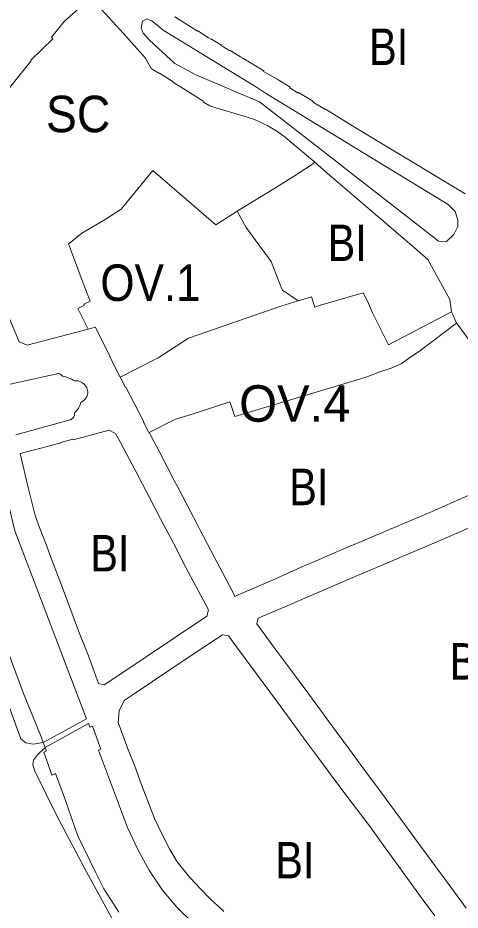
# Model space of a CAD drawing. Extents: x -650451 to -642268, y -1075216 to -1066610.
# Drawn here: x -647183 to -647037.6, y -1071143.1 to -1070849.7 of the extents above; entities that cross this region are included whole.
import ezdxf

# ---------------------------------------------------------------- set-up
doc = ezdxf.new("R2010")
doc.units = 0
doc.header["$LTSCALE"] = 4.8
for name, color, linetype, lineweight in [('1', 7, 'Continuous', 13), ('11', 7, 'Continuous', 13), ('15', 7, 'Continuous', 13), ('17', 7, 'Continuous', 13), ('2', 7, 'Continuous', 13), ('40', 7, 'Continuous', 13), ('45', 7, 'Continuous', 13)]:
    doc.layers.add(name, color=color, linetype=linetype, lineweight=lineweight)
doc.layers.add('62', color=7, linetype='Continuous')

msp = doc.modelspace()

# ---------------------------------------------------------------- linework, layer by layer
at = {"layer": '1'}
for points in [[(-647204.055, -1071005.609), (-647203.96, -1071005.88), (-647199.63, -1071026.94), (-647195.64, -1071044.04), (-647194.61, -1071048.68), (-647192.72, -1071055.27), (-647189.68, -1071065.99), (-647181.99, -1071086.74), (-647180.4, -1071088.08), (-647177.94, -1071088.5), (-647174.64, -1071088.01), (-647174.03, -1071089.6)], [(-647174.03, -1071089.6), (-647176.58, -1071092.03), (-647177.89, -1071093.78), (-647178.11, -1071095.31), (-647177.46, -1071097.42), (-647170.18, -1071112.08), (-647161.13, -1071129.3), (-647146.28, -1071156.35), (-647135.21, -1071176.44), (-647130.1, -1071184.33), (-647129.04, -1071186.06), (-647125.44, -1071192.58), (-647123.7, -1071196.19), (-647106.7, -1071234.45), (-647104.17, -1071235.6)]]:
    msp.add_lwpolyline(points, dxfattribs=at)
at = {"layer": '11'}
for points in [[(-647159.85, -1070952.1), (-647163.28, -1070945.32), (-647161.07, -1070944.22), (-647161.27, -1070943.82), (-647159.26, -1070942.81), (-647161.48, -1070936.91), (-647165.05, -1070927.47), (-647166.38, -1070924.05), (-647165.6, -1070923.42), (-647161.98, -1070920.55), (-647154.33, -1070916.01), (-647148.98, -1070912.65), (-647138.65, -1070899.94), (-647117.95, -1070917.77), (-647110.92, -1070913.23)], [(-647110.92, -1070913.23), (-647107.9, -1070918.58), (-647104.06, -1070923.89), (-647099.76, -1070929.83), (-647096.5, -1070937.98), (-647095.97, -1070939.29), (-647090.82, -1070942.76)], [(-647090.82, -1070942.76), (-647086.45, -1070941.45), (-647085.35, -1070944.79), (-647083.51, -1070944.2), (-647069.41, -1070940.13), (-647068.07, -1070942.91), (-647066.38, -1070946.67), (-647061.16, -1070957.22), (-647040.4, -1070946.32)], [(-647090.82, -1070942.76), (-647096.57, -1070944.49), (-647126.93, -1070955.01), (-647136.81, -1070961.5), (-647149.39, -1070967.8)], [(-647149.39, -1070967.8), (-647136.81, -1070961.5), (-647126.93, -1070955.01), (-647096.57, -1070944.49), (-647090.82, -1070942.76)], [(-647040.4, -1070946.32), (-647039.98, -1070947.27), (-647038.77, -1070950.05)], [(-647038.77, -1070950.05), (-647050.95, -1070959.26), (-647054.07, -1070961.43), (-647056.94, -1070963.42), (-647060.27, -1070964.9), (-647063.97, -1070966.14), (-647067.95, -1070967.65), (-647071.8, -1070968.86), (-647111.62, -1070980.84), (-647112.64, -1070977.86), (-647113.29, -1070975.92), (-647118.98, -1070977.8), (-647122.66, -1070978.98), (-647127.1, -1070980.41), (-647131.11, -1070981.71), (-647139.77, -1070986.03)], [(-647149.39, -1070967.8), (-647152.75, -1070961.18), (-647152.62, -1070961.11), (-647157.5, -1070951.41), (-647157.59, -1070951.46), (-647159.85, -1070952.1)], [(-647139.77, -1070986.03), (-647139.82, -1070985.92), (-647139.98, -1070986.03), (-647141.67, -1070982.64), (-647141.54, -1070982.55), (-647147.47, -1070971.18), (-647147.59, -1070971.24), (-647149.39, -1070967.8)]]:
    msp.add_lwpolyline(points, dxfattribs=at)
at = {"layer": '15'}
for points in [[(-647159.11, -1070843.05), (-647167.65, -1070850.81), (-647171.97, -1070856.04), (-647171.49, -1070856.55), (-647178.72, -1070863.64), (-647178.59, -1070863.81), (-647184.47, -1070871.02), (-647191.27, -1070879.56), (-647198.26, -1070888.32), (-647203.11, -1070894.33), (-647205.72, -1070897.57), (-647206.05, -1070898.36), (-647205.89, -1070899.27), (-647200.92, -1070911.38), (-647195.82, -1070923.93), (-647191.5, -1070934.48), (-647189.1, -1070940.36), (-647187.61, -1070944.13), (-647182.58, -1070956.24), (-647179.88, -1070957.38), (-647159.85, -1070952.1)], [(-647085.4, -1070897.14), (-647095.52, -1070888.57), (-647098.18, -1070886.71), (-647100.79, -1070885.17), (-647105.19, -1070883.09), (-647108.31, -1070882.14), (-647117.94, -1070879.25), (-647119.85, -1070878.57), (-647122, -1070877.41), (-647121.89, -1070877.25), (-647129.57, -1070872.37), (-647132.03, -1070870.82), (-647131.98, -1070870.73), (-647136.41, -1070867.92), (-647136.47, -1070868), (-647139.02, -1070866.44), (-647141.09, -1070862.83), (-647148.3, -1070854.79), (-647157.95, -1070844.35)], [(-647131.43, -1070849.34), (-647123.88, -1070854.09), (-647123.82, -1070853.99), (-647120.31, -1070856.28), (-647119.59, -1070856.68), (-647119.55, -1070856.6), (-647116.09, -1070858.66), (-647116.16, -1070858.77), (-647113.25, -1070860.52), (-647113.19, -1070860.43), (-647109.74, -1070862.55), (-647109.06, -1070862.97), (-647102.16, -1070867.16), (-647102.27, -1070867.33), (-647097.73, -1070869.9), (-647093.48, -1070872.53), (-647093.57, -1070872.69), (-647090.78, -1070874.43), (-647090.69, -1070874.28), (-647086.39, -1070876.9), (-647085.74, -1070877.4), (-647085.79, -1070877.49), (-647081.89, -1070879.84), (-647081.84, -1070879.77), (-647081.35, -1070880.06), (-647074.06, -1070884.49), (-647063.75, -1070890.75), (-647052.83, -1070897.35), (-647035.98, -1070907.53)], [(-647040.4, -1070946.32), (-647041.01, -1070942.31), (-647048.23, -1070929.16), (-647052.6, -1070925.35), (-647055.69, -1070922.66), (-647062.48, -1070916.84), (-647062.93, -1070916.46), (-647063.93, -1070915.6), (-647069.27, -1070911.03), (-647078.43, -1070903.2), (-647080.53, -1070901.41), (-647085.4, -1070897.14)], [(-647174.64, -1071088.01), (-647160.4, -1071080.2), (-647184, -1071018.37), (-647190.24, -1070992.73), (-647199.63, -1070950.26), (-647202.86, -1070940.4), (-647204.22, -1070937.43), (-647205.57, -1070934.86), (-647207.86, -1070930.75), (-647207.09, -1070930.4), (-647209.82, -1070924.75), (-647210.86, -1070925.29), (-647215.03, -1070918.17), (-647220.39, -1070910.9), (-647230.25, -1070922.01)], [(-647038.77, -1070950.05), (-647039.98, -1070947.27), (-647040.4, -1070946.32)], [(-647034.09, -1070956.5), (-647038.19, -1070950.73), (-647038.77, -1070950.05)], [(-647159.85, -1070952.1), (-647157.59, -1070951.46), (-647157.5, -1070951.41), (-647152.62, -1070961.11), (-647152.75, -1070961.18), (-647149.39, -1070967.8)], [(-647183.62, -1070986.82), (-647165.84, -1070981.83), (-647165.677, -1070981.79), (-647165.513, -1070981.734), (-647165.35, -1070981.66), (-647165.191, -1070981.569), (-647165.04, -1070981.459), (-647164.897, -1070981.333), (-647164.768, -1070981.19), (-647164.653, -1070981.035), (-647164.555, -1070980.868), (-647164.475, -1070980.692), (-647164.415, -1070980.512), (-647164.374, -1070980.329), (-647164.353, -1070980.147), (-647164.349, -1070979.968), (-647164.362, -1070979.795), (-647164.39, -1070979.63), (-647164.023, -1070979.279), (-647163.679, -1070978.898), (-647163.364, -1070978.49), (-647163.079, -1070978.058), (-647162.828, -1070977.607), (-647162.612, -1070977.138), (-647162.432, -1070976.658), (-647162.29, -1070976.17), (-647162.006, -1070976), (-647161.732, -1070975.812), (-647161.468, -1070975.606), (-647161.218, -1070975.384), (-647160.981, -1070975.147), (-647160.761, -1070974.896), (-647160.556, -1070974.633), (-647160.37, -1070974.36), (-647160.201, -1070973.97), (-647160.079, -1070973.551), (-647160.012, -1070973.112), (-647160.004, -1070972.664), (-647160.055, -1070972.219), (-647160.163, -1070971.788), (-647160.324, -1070971.382), (-647160.53, -1070971.01), (-647160.674, -1070970.78), (-647160.837, -1070970.558), (-647161.018, -1070970.343), (-647161.216, -1070970.14), (-647161.431, -1070969.949), (-647161.66, -1070969.773), (-647161.903, -1070969.613), (-647162.158, -1070969.471), (-647162.423, -1070969.349), (-647162.695, -1070969.246), (-647162.972, -1070969.164), (-647163.253, -1070969.103), (-647163.534, -1070969.062), (-647163.813, -1070969.042), (-647164.089, -1070969.042), (-647164.36, -1070969.06), (-647164.82, -1070968.802), (-647165.29, -1070968.561), (-647165.77, -1070968.339), (-647166.259, -1070968.136), (-647166.756, -1070967.952), (-647167.259, -1070967.788), (-647167.768, -1070967.644), (-647168.28, -1070967.52), (-647168.478, -1070967.276), (-647168.724, -1070967.059), (-647169.013, -1070966.883), (-647169.332, -1070966.757), (-647169.669, -1070966.69), (-647170.007, -1070966.683), (-647170.332, -1070966.732), (-647170.63, -1070966.83), (-647187.45, -1070970.63)], [(-647149.39, -1070967.8), (-647147.59, -1070971.24), (-647147.47, -1070971.18), (-647141.54, -1070982.55), (-647141.67, -1070982.64), (-647139.98, -1070986.03), (-647139.82, -1070985.92), (-647139.77, -1070986.03)], [(-647139.77, -1070986.03), (-647136.42, -1070992.4), (-647131.57, -1071001.79), (-647130.42, -1071003.99), (-647126.2, -1071012.05), (-647124.16, -1071016), (-647123.01, -1071018.21), (-647118.46, -1071026.92), (-647115.64, -1071032.28), (-647112.2, -1071038.81), (-647111.69, -1071039.93), (-647111.46, -1071039.83), (-647110.53, -1071039.41), (-647098.25, -1071034.12), (-647098.03, -1071034.02), (-647088.61, -1071029.83), (-647084.94, -1071028.2), (-647077.91, -1071025.19), (-647066.72, -1071020.44), (-647062.38, -1071018.6), (-647057.91, -1071016.75), (-647046.73, -1071012.03), (-647039.7, -1071008.85), (-647030.09, -1071004.71)], [(-647034.05, -1071017.19), (-647042.97, -1071021.07), (-647049.89, -1071023.99), (-647056.91, -1071026.94), (-647063.71, -1071029.85), (-647072.13, -1071033.43), (-647080, -1071036.81), (-647087.87, -1071040.16), (-647093.7, -1071042.7), (-647103.94, -1071047.15), (-647104.42, -1071049.02), (-647098.81, -1071056.61), (-647094.28, -1071062.75), (-647086.95, -1071072.55), (-647080.49, -1071081.41), (-647074, -1071090.26), (-647069.57, -1071096.31), (-647063.44, -1071104.55), (-647057.61, -1071112.44), (-647051.99, -1071120.09), (-647040.61, -1071135.59), (-647035.55, -1071142.45)], [(-647045.94, -1071145.04), (-647049.72, -1071139.82), (-647052.02, -1071136.62), (-647057.7, -1071128.79), (-647061.95, -1071123.11), (-647067.4, -1071115.37), (-647073.12, -1071107.95), (-647078.46, -1071100.83), (-647083.72, -1071093.74), (-647087.31, -1071088.82), (-647090.86, -1071084.05), (-647094.36, -1071079.2), (-647097.98, -1071074.28), (-647104.55, -1071065.44), (-647111.07, -1071056.53), (-647113.73, -1071052.94), (-647115.73, -1071052.54), (-647127.7, -1071060.49), (-647144.46, -1071071.76), (-647148, -1071074.23), (-647149.73, -1071077.63), (-647150.04, -1071081.39), (-647146.78, -1071090.05), (-647144.56, -1071095.83), (-647142.43, -1071101.58), (-647140.25, -1071107.27), (-647138.05, -1071112.99), (-647135.48, -1071118.5), (-647133.11, -1071122.94), (-647130.57, -1071127.29), (-647126.96, -1071131.77), (-647126.3, -1071132.51), (-647122.81, -1071136.22), (-647119.63, -1071139.51), (-647116.09, -1071142.83), (-647115.24, -1071143.6)], [(-647125.39, -1071147.43), (-647130.77, -1071142.19), (-647135.45, -1071136.55), (-647139.72, -1071130.15), (-647143.58, -1071123.16), (-647146.94, -1071115.94), (-647156.53, -1071090.49), (-647155.66, -1071090.17), (-647158.43, -1071082.62), (-647159.3, -1071082.95), (-647159.77, -1071081.77), (-647174.03, -1071089.6), (-647174.64, -1071088.01)]]:
    msp.add_lwpolyline(points, dxfattribs=at)
for points in [[(-647142.02, -1070850.81), (-647142.49, -1070852.95), (-647141.78, -1070854.71), (-647139.73, -1070857.02), (-647131.43, -1070864.72), (-647124.51, -1070868.42), (-647106.9, -1070875.89), (-647103.57, -1070877.32), (-647077.16, -1070897.85), (-647075.9, -1070898.84), (-647050.33, -1070918.71), (-647044.71, -1070923.08), (-647042.06, -1070923.25), (-647039.69, -1070920.97), (-647038.35, -1070918.28), (-647038.36, -1070916.27), (-647039.23, -1070913.32), (-647041.52, -1070911.06), (-647071.49, -1070892.79), (-647072.94, -1070891.9), (-647101.59, -1070874.43), (-647104.58, -1070872.51), (-647135.27, -1070853.78), (-647136.62, -1070852.49), (-647138.98, -1070850.63), (-647140.46, -1070849.98)], [(-647120.88, -1071046.5), (-647120.35, -1071044.37), (-647123.72, -1071037.99), (-647127.72, -1071030.49), (-647131.87, -1071022.49), (-647136.1, -1071014.48), (-647139.72, -1071007.46), (-647144.4, -1070998.49), (-647149.25, -1070989.35), (-647150.85, -1070986.34), (-647153.01, -1070985.33), (-647164.84, -1070988.42), (-647164.9, -1070988.27), (-647168.9, -1070989.33), (-647168.86, -1070989.48), (-647172.48, -1070990.42), (-647182.23, -1070992.92), (-647179.69, -1071003.72), (-647177.35, -1071013.31), (-647175.82, -1071017.26), (-647174.63, -1071020.34), (-647173.5, -1071023.44), (-647172.26, -1071026.85), (-647168.69, -1071036.25), (-647166.23, -1071042.76), (-647162.69, -1071052.17), (-647159.8, -1071059.54), (-647156.48, -1071068.56), (-647154.59, -1071069.06), (-647147.46, -1071064.28), (-647140.81, -1071059.84), (-647131.8, -1071053.75)]]:
    msp.add_lwpolyline(points, close=True, dxfattribs=at)
at = {"layer": '17'}
for points in [[(-647159.85, -1070952.1), (-647179.88, -1070957.38), (-647182.58, -1070956.24), (-647187.61, -1070944.13), (-647189.1, -1070940.36), (-647191.5, -1070934.48), (-647195.82, -1070923.93), (-647200.92, -1070911.38), (-647205.89, -1070899.27), (-647206.05, -1070898.36), (-647205.72, -1070897.57), (-647203.11, -1070894.33), (-647198.26, -1070888.32), (-647191.27, -1070879.56), (-647184.47, -1070871.02), (-647178.59, -1070863.81), (-647178.72, -1070863.64), (-647171.49, -1070856.55), (-647171.97, -1070856.04), (-647167.65, -1070850.81), (-647159.11, -1070843.05)], [(-647157.95, -1070844.35), (-647148.3, -1070854.79), (-647141.09, -1070862.83), (-647139.02, -1070866.44), (-647136.47, -1070868), (-647136.41, -1070867.92), (-647131.98, -1070870.73), (-647132.03, -1070870.82), (-647129.57, -1070872.37), (-647121.89, -1070877.25), (-647122, -1070877.41), (-647119.85, -1070878.57), (-647117.94, -1070879.25), (-647108.31, -1070882.14), (-647105.19, -1070883.09), (-647100.79, -1070885.17), (-647098.18, -1070886.71), (-647095.52, -1070888.57), (-647085.4, -1070897.14)], [(-647085.4, -1070897.14), (-647086.47, -1070898), (-647090.87, -1070900.84), (-647091.46, -1070901.32), (-647098.82, -1070905.97), (-647110.92, -1070913.23)], [(-647110.92, -1070913.23), (-647117.95, -1070917.77), (-647138.65, -1070899.94), (-647148.98, -1070912.65), (-647154.33, -1070916.01), (-647161.98, -1070920.55), (-647165.6, -1070923.42), (-647166.38, -1070924.05), (-647165.05, -1070927.47), (-647161.48, -1070936.91), (-647159.26, -1070942.81), (-647161.27, -1070943.82), (-647161.07, -1070944.22), (-647163.28, -1070945.32), (-647159.85, -1070952.1)]]:
    msp.add_lwpolyline(points, dxfattribs=at)
at = {"layer": '2'}
for points in [[(-647035.98, -1070907.53), (-647052.83, -1070897.35), (-647063.75, -1070890.75), (-647074.06, -1070884.49), (-647081.35, -1070880.06), (-647081.84, -1070879.77), (-647081.89, -1070879.84), (-647085.79, -1070877.49), (-647085.74, -1070877.4), (-647086.39, -1070876.9), (-647090.69, -1070874.28), (-647090.78, -1070874.43), (-647093.57, -1070872.69), (-647093.48, -1070872.53), (-647097.73, -1070869.9), (-647102.27, -1070867.33), (-647102.16, -1070867.16), (-647109.06, -1070862.97), (-647109.74, -1070862.55), (-647113.19, -1070860.43), (-647113.25, -1070860.52), (-647116.16, -1070858.77), (-647116.09, -1070858.66), (-647119.55, -1070856.6), (-647119.59, -1070856.68), (-647120.31, -1070856.28), (-647123.82, -1070853.99), (-647123.88, -1070854.09), (-647131.43, -1070849.34)], [(-647110.92, -1070913.23), (-647098.82, -1070905.97), (-647091.46, -1070901.32), (-647090.87, -1070900.84), (-647086.47, -1070898), (-647085.4, -1070897.14)], [(-647085.4, -1070897.14), (-647080.53, -1070901.41), (-647078.43, -1070903.2), (-647069.27, -1070911.03), (-647063.93, -1070915.6), (-647062.93, -1070916.46), (-647062.48, -1070916.84), (-647055.69, -1070922.66), (-647052.6, -1070925.35), (-647048.23, -1070929.16), (-647041.01, -1070942.31), (-647040.4, -1070946.32)], [(-647090.82, -1070942.76), (-647095.97, -1070939.29), (-647096.5, -1070937.98), (-647099.76, -1070929.83), (-647104.06, -1070923.89), (-647107.9, -1070918.58), (-647110.92, -1070913.23)], [(-647040.4, -1070946.32), (-647061.16, -1070957.22), (-647066.38, -1070946.67), (-647068.07, -1070942.91), (-647069.41, -1070940.13), (-647083.51, -1070944.2), (-647085.35, -1070944.79), (-647086.45, -1070941.45), (-647090.82, -1070942.76)], [(-647139.77, -1070986.03), (-647131.11, -1070981.71), (-647127.1, -1070980.41), (-647122.66, -1070978.98), (-647118.98, -1070977.8), (-647113.29, -1070975.92), (-647112.64, -1070977.86), (-647111.62, -1070980.84), (-647071.8, -1070968.86), (-647067.95, -1070967.65), (-647063.97, -1070966.14), (-647060.27, -1070964.9), (-647056.94, -1070963.42), (-647054.07, -1070961.43), (-647050.95, -1070959.26), (-647038.77, -1070950.05)], [(-647038.77, -1070950.05), (-647038.19, -1070950.73), (-647034.09, -1070956.5)], [(-647030.09, -1071004.71), (-647039.7, -1071008.85), (-647046.73, -1071012.03), (-647057.91, -1071016.75), (-647062.38, -1071018.6), (-647066.72, -1071020.44), (-647077.91, -1071025.19), (-647084.94, -1071028.2), (-647088.61, -1071029.83), (-647098.03, -1071034.02), (-647098.25, -1071034.12), (-647110.53, -1071039.41), (-647111.46, -1071039.83), (-647111.69, -1071039.93), (-647112.2, -1071038.81), (-647115.64, -1071032.28), (-647118.46, -1071026.92), (-647123.01, -1071018.21), (-647124.16, -1071016), (-647126.2, -1071012.05), (-647130.42, -1071003.99), (-647131.57, -1071001.79), (-647136.42, -1070992.4), (-647139.77, -1070986.03)], [(-647035.55, -1071142.45), (-647040.61, -1071135.59), (-647051.99, -1071120.09), (-647057.61, -1071112.44), (-647063.44, -1071104.55), (-647069.57, -1071096.31), (-647074, -1071090.26), (-647080.49, -1071081.41), (-647086.95, -1071072.55), (-647094.28, -1071062.75), (-647098.81, -1071056.61), (-647104.42, -1071049.02), (-647103.94, -1071047.15), (-647093.7, -1071042.7), (-647087.87, -1071040.16), (-647080, -1071036.81), (-647072.13, -1071033.43), (-647063.71, -1071029.85), (-647056.91, -1071026.94), (-647049.89, -1071023.99), (-647042.97, -1071021.07), (-647034.05, -1071017.19)], [(-647115.24, -1071143.6), (-647116.09, -1071142.83), (-647119.63, -1071139.51), (-647122.81, -1071136.22), (-647126.3, -1071132.51), (-647126.96, -1071131.77), (-647130.57, -1071127.29), (-647133.11, -1071122.94), (-647135.48, -1071118.5), (-647138.05, -1071112.99), (-647140.25, -1071107.27), (-647142.43, -1071101.58), (-647144.56, -1071095.83), (-647146.78, -1071090.05), (-647150.04, -1071081.39), (-647149.73, -1071077.63), (-647148, -1071074.23), (-647144.46, -1071071.76), (-647127.7, -1071060.49), (-647115.73, -1071052.54), (-647113.73, -1071052.94), (-647111.07, -1071056.53), (-647104.55, -1071065.44), (-647097.98, -1071074.28), (-647094.36, -1071079.2), (-647090.86, -1071084.05), (-647087.31, -1071088.82), (-647083.72, -1071093.74), (-647078.46, -1071100.83), (-647073.12, -1071107.95), (-647067.4, -1071115.37), (-647061.95, -1071123.11), (-647057.7, -1071128.79), (-647052.02, -1071136.62), (-647049.72, -1071139.82), (-647045.94, -1071145.04)]]:
    msp.add_lwpolyline(points, dxfattribs=at)
msp.add_lwpolyline([(-647120.88, -1071046.5), (-647131.8, -1071053.75), (-647140.81, -1071059.84), (-647147.46, -1071064.28), (-647154.59, -1071069.06), (-647156.48, -1071068.56), (-647159.8, -1071059.54), (-647162.69, -1071052.17), (-647166.23, -1071042.76), (-647168.69, -1071036.25), (-647172.26, -1071026.85), (-647173.5, -1071023.44), (-647174.63, -1071020.34), (-647175.82, -1071017.26), (-647177.35, -1071013.31), (-647179.69, -1071003.72), (-647182.23, -1070992.92), (-647172.48, -1070990.42), (-647168.86, -1070989.48), (-647168.9, -1070989.33), (-647164.9, -1070988.27), (-647164.84, -1070988.42), (-647153.01, -1070985.33), (-647150.85, -1070986.34), (-647149.25, -1070989.35), (-647144.4, -1070998.49), (-647139.72, -1071007.46), (-647136.1, -1071014.48), (-647131.87, -1071022.49), (-647127.72, -1071030.49), (-647123.72, -1071037.99), (-647120.35, -1071044.37)], close=True, dxfattribs=at)
at = {"layer": '40'}
msp.add_lwpolyline([(-647142.02, -1070850.81), (-647140.46, -1070849.98), (-647138.98, -1070850.63), (-647136.62, -1070852.49), (-647135.27, -1070853.78), (-647104.58, -1070872.51), (-647101.59, -1070874.43), (-647072.94, -1070891.9), (-647071.49, -1070892.79), (-647041.52, -1070911.06), (-647039.23, -1070913.32), (-647038.36, -1070916.27), (-647038.35, -1070918.28), (-647039.69, -1070920.97), (-647042.06, -1070923.25), (-647044.71, -1070923.08), (-647050.33, -1070918.71), (-647075.9, -1070898.84), (-647077.16, -1070897.85), (-647103.57, -1070877.32), (-647106.9, -1070875.89), (-647124.51, -1070868.42), (-647131.43, -1070864.72), (-647139.73, -1070857.02), (-647141.78, -1070854.71), (-647142.49, -1070852.95)], close=True, dxfattribs=at)
for points in [[(-647226.17, -1070928.21), (-647220.36, -1070939.77), (-647219.79, -1070939.58), (-647216.55, -1070948.32), (-647210.6, -1070978.71), (-647208.38, -1070985.66), (-647209.12, -1070986.08), (-647207.7, -1070991.72), (-647206.44, -1070991.45), (-647204.93, -1070999.15), (-647194.45, -1071036.17), (-647181.14, -1071071.84), (-647175.35, -1071086.17), (-647174.64, -1071088.01)], [(-647187.45, -1070970.63), (-647170.63, -1070966.83), (-647170.332, -1070966.732), (-647170.007, -1070966.683), (-647169.669, -1070966.69), (-647169.332, -1070966.757), (-647169.013, -1070966.883), (-647168.724, -1070967.059), (-647168.478, -1070967.276), (-647168.28, -1070967.52), (-647167.768, -1070967.644), (-647167.259, -1070967.788), (-647166.756, -1070967.952), (-647166.259, -1070968.136), (-647165.77, -1070968.339), (-647165.29, -1070968.561), (-647164.82, -1070968.802), (-647164.36, -1070969.06), (-647164.089, -1070969.042), (-647163.813, -1070969.042), (-647163.534, -1070969.062), (-647163.253, -1070969.103), (-647162.972, -1070969.164), (-647162.695, -1070969.246), (-647162.423, -1070969.349), (-647162.158, -1070969.471), (-647161.903, -1070969.613), (-647161.66, -1070969.773), (-647161.431, -1070969.949), (-647161.216, -1070970.14), (-647161.018, -1070970.343), (-647160.837, -1070970.558), (-647160.674, -1070970.78), (-647160.53, -1070971.01), (-647160.324, -1070971.382), (-647160.163, -1070971.788), (-647160.055, -1070972.219), (-647160.004, -1070972.664), (-647160.012, -1070973.112), (-647160.079, -1070973.551), (-647160.201, -1070973.97), (-647160.37, -1070974.36), (-647160.556, -1070974.633), (-647160.761, -1070974.896), (-647160.981, -1070975.147), (-647161.218, -1070975.384), (-647161.468, -1070975.606), (-647161.732, -1070975.812), (-647162.006, -1070976), (-647162.29, -1070976.17), (-647162.432, -1070976.658), (-647162.612, -1070977.138), (-647162.828, -1070977.607), (-647163.079, -1070978.058), (-647163.364, -1070978.49), (-647163.679, -1070978.898), (-647164.023, -1070979.279), (-647164.39, -1070979.63), (-647164.362, -1070979.795), (-647164.349, -1070979.968), (-647164.353, -1070980.147), (-647164.374, -1070980.329), (-647164.415, -1070980.512), (-647164.475, -1070980.692), (-647164.555, -1070980.868), (-647164.653, -1070981.035), (-647164.768, -1070981.19), (-647164.897, -1070981.333), (-647165.04, -1070981.459), (-647165.191, -1070981.569), (-647165.35, -1070981.66), (-647165.513, -1070981.734), (-647165.677, -1070981.79), (-647165.84, -1070981.83), (-647183.62, -1070986.82)], [(-647174.64, -1071088.01), (-647177.94, -1071088.5), (-647180.4, -1071088.08), (-647181.99, -1071086.74), (-647189.68, -1071065.99), (-647192.72, -1071055.27), (-647194.61, -1071048.68), (-647195.64, -1071044.04), (-647199.63, -1071026.94), (-647203.96, -1071005.88), (-647204.055, -1071005.609)], [(-647104.17, -1071235.6), (-647106.7, -1071234.45), (-647123.7, -1071196.19), (-647125.44, -1071192.58), (-647129.04, -1071186.06), (-647130.1, -1071184.33), (-647135.21, -1071176.44), (-647146.28, -1071156.35), (-647161.13, -1071129.3), (-647170.18, -1071112.08), (-647177.46, -1071097.42), (-647178.11, -1071095.31), (-647177.89, -1071093.78), (-647176.58, -1071092.03), (-647174.03, -1071089.6)], [(-647174.03, -1071089.6), (-647173.58, -1071090.76), (-647174.46, -1071091.16), (-647172.36, -1071097.12), (-647171.8, -1071098.72), (-647170.65, -1071098.22), (-647167.29, -1071107.02), (-647163.39, -1071118.52), (-647157.4, -1071130.91), (-647154.71, -1071136.17), (-647149.79, -1071143.81)]]:
    msp.add_lwpolyline(points, dxfattribs=at)
at = {"layer": '45'}
for points in [[(-647230.25, -1070922.01), (-647220.39, -1070910.9), (-647215.03, -1070918.17), (-647210.86, -1070925.29), (-647209.82, -1070924.75), (-647207.09, -1070930.4), (-647207.86, -1070930.75), (-647205.57, -1070934.86), (-647204.22, -1070937.43), (-647202.86, -1070940.4), (-647199.63, -1070950.26), (-647190.24, -1070992.73), (-647184, -1071018.37), (-647160.4, -1071080.2), (-647174.64, -1071088.01)], [(-647174.64, -1071088.01), (-647175.35, -1071086.17), (-647181.14, -1071071.84), (-647194.45, -1071036.17), (-647204.93, -1070999.15), (-647206.44, -1070991.45), (-647207.7, -1070991.72), (-647209.12, -1070986.08), (-647208.38, -1070985.66), (-647210.6, -1070978.71), (-647216.55, -1070948.32), (-647219.79, -1070939.58), (-647220.36, -1070939.77), (-647226.17, -1070928.21), (-647230.25, -1070922.01)], [(-647174.03, -1071089.6), (-647159.77, -1071081.77), (-647159.3, -1071082.95), (-647158.43, -1071082.62), (-647155.66, -1071090.17), (-647156.53, -1071090.49), (-647146.94, -1071115.94), (-647143.58, -1071123.16), (-647139.72, -1071130.15), (-647135.45, -1071136.55), (-647130.77, -1071142.19), (-647125.39, -1071147.43)], [(-647149.79, -1071143.81), (-647154.71, -1071136.17), (-647157.4, -1071130.91), (-647163.39, -1071118.52), (-647167.29, -1071107.02), (-647170.65, -1071098.22), (-647171.8, -1071098.72), (-647172.36, -1071097.12), (-647174.46, -1071091.16), (-647173.58, -1071090.76), (-647174.03, -1071089.6)]]:
    msp.add_lwpolyline(points, dxfattribs=at)

# ---------------------------------------------------------------- texts
at = {"layer": '62'}
for s, width, p in [('BI', 0.85, (-647067.524, -1070865.206)), ('SC', 0.95, (-647173.766, -1070887.288)), ('BI', 0.85, (-647081.166, -1070929.66)), ('OV.1', 0.9, (-647155.86, -1070942.785)), ('BI', 0.85, (-647093.784, -1071009.959)), ('BI', 0.85, (-647159.17, -1071031.754)), ('BI', 0.85, (-647041.016, -1071067.315)), ('BI', 0.85, (-647098.372, -1071132.701))]:
    msp.add_text(s, height=12, dxfattribs=dict(at, width=width)).set_placement(p)
msp.add_text('OV.4', height=12, dxfattribs=at).set_placement((-647110.244, -1070982.508))

doc.saveas('drawing.dxf')
